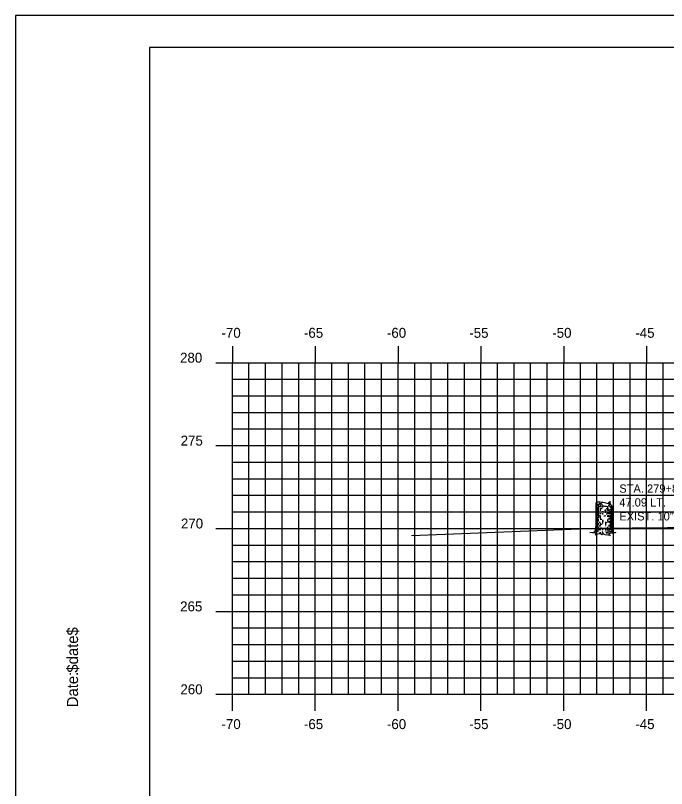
# Model space of a CAD drawing. Extents: x 854899 to 855069, y 366268 to 366378.
# Drawn here: x 854898.68 to 854937.97, y 366331.55 to 366378.18 of the extents above; entities that cross this region are included whole.
import ezdxf

# ---------------------------------------------------------------- set-up
doc = ezdxf.new("R2010")
doc.units = 0
for name, color, linetype in [('BORDER', 7, 'Continuous'), ('D_Text_Monospaced', 7, 'Continuous'), ('H_V ANNOTATION', 7, 'Continuous'), ('MAJOR', 7, 'Continuous'), ('MINOR', 7, 'Continuous'), ('PLOT BOUNDARY', 7, 'Continuous'), ('S_Roadway_Centerline', 7, 'Continuous'), ('S_Trees_Decid_NonPay', 7, 'Continuous')]:
    doc.layers.add(name, color=color, linetype=linetype)

msp = doc.modelspace()

# ---------------------------------------------------------------- linework, layer by layer
at = {"layer": 'BORDER'}
for p, q in [((855066.774, 366376.236), (854906.774, 366376.236)), ((854906.774, 366376.236), (854906.774, 366271.236))]:
    msp.add_line(p, q, dxfattribs=at)
at = {"layer": 'MAJOR'}
for p, q in [((854911.774, 366358.238), (854911.774, 366357.236)), ((854916.774, 366358.238), (854916.774, 366357.236)), ((854921.774, 366358.238), (854921.774, 366357.236)), ((854926.774, 366358.238), (854926.774, 366357.236)), ((854931.774, 366358.238), (854931.774, 366357.236)), ((854936.774, 366358.238), (854936.774, 366357.236)), ((854910.772, 366357.236), (854911.774, 366357.236)), ((854911.774, 366357.236), (855051.774, 366357.236)), ((854911.774, 366337.236), (854911.774, 366357.236)), ((854911.774, 366337.236), (854911.774, 366357.236)), ((854911.774, 366357.236), (855051.774, 366357.236)), ((854916.774, 366337.236), (854916.774, 366357.236)), ((854921.774, 366337.236), (854921.774, 366357.236)), ((854926.774, 366337.236), (854926.774, 366357.236)), ((854931.774, 366337.236), (854931.774, 366357.236)), ((854936.774, 366337.236), (854936.774, 366357.236)), ((854910.772, 366352.236), (854911.774, 366352.236)), ((854911.774, 366352.236), (855051.774, 366352.236)), ((854910.772, 366347.236), (854911.774, 366347.236)), ((854911.774, 366347.236), (855051.774, 366347.236)), ((854910.772, 366342.236), (854911.774, 366342.236)), ((854911.774, 366342.236), (855051.774, 366342.236)), ((854910.772, 366337.236), (854911.774, 366337.236)), ((854911.774, 366337.236), (855051.774, 366337.236)), ((854911.774, 366337.236), (855051.774, 366337.236)), ((854911.774, 366336.234), (854911.774, 366337.236)), ((854916.774, 366336.234), (854916.774, 366337.236)), ((854921.774, 366336.234), (854921.774, 366337.236)), ((854926.774, 366336.234), (854926.774, 366337.236)), ((854931.774, 366336.234), (854931.774, 366337.236)), ((854936.774, 366336.234), (854936.774, 366337.236))]:
    msp.add_line(p, q, dxfattribs=at)
at = {"layer": 'MINOR'}
for p, q in [((854911.774, 366337.236), (854911.774, 366357.236)), ((854912.774, 366337.236), (854912.774, 366357.236)), ((854913.774, 366337.236), (854913.774, 366357.236)), ((854914.774, 366337.236), (854914.774, 366357.236)), ((854915.774, 366337.236), (854915.774, 366357.236)), ((854917.774, 366337.236), (854917.774, 366357.236)), ((854918.774, 366337.236), (854918.774, 366357.236)), ((854919.774, 366337.236), (854919.774, 366357.236)), ((854920.774, 366337.236), (854920.774, 366357.236)), ((854922.774, 366337.236), (854922.774, 366357.236)), ((854923.774, 366337.236), (854923.774, 366357.236)), ((854924.774, 366337.236), (854924.774, 366357.236)), ((854925.774, 366337.236), (854925.774, 366357.236)), ((854927.774, 366337.236), (854927.774, 366357.236)), ((854928.774, 366337.236), (854928.774, 366357.236)), ((854929.774, 366337.236), (854929.774, 366357.236)), ((854930.774, 366337.236), (854930.774, 366357.236)), ((854932.774, 366337.236), (854932.774, 366357.236)), ((854933.774, 366337.236), (854933.774, 366357.236)), ((854934.774, 366337.236), (854934.774, 366357.236)), ((854935.774, 366337.236), (854935.774, 366357.236)), ((854937.774, 366337.236), (854937.774, 366357.236)), ((854911.774, 366356.236), (855051.774, 366356.236)), ((854911.774, 366356.236), (854912.776, 366356.236)), ((854911.774, 366355.236), (855051.774, 366355.236)), ((854911.774, 366355.236), (854912.776, 366355.236)), ((854911.774, 366354.236), (855051.774, 366354.236)), ((854911.774, 366354.236), (854912.776, 366354.236)), ((854911.774, 366353.236), (855051.774, 366353.236)), ((854911.774, 366353.236), (854912.776, 366353.236)), ((854911.774, 366351.236), (855051.774, 366351.236)), ((854911.774, 366351.236), (854912.776, 366351.236)), ((854911.774, 366350.236), (855051.774, 366350.236)), ((854911.774, 366350.236), (854912.776, 366350.236)), ((854911.774, 366349.236), (855051.774, 366349.236)), ((854911.774, 366349.236), (854912.776, 366349.236)), ((854911.774, 366348.236), (855051.774, 366348.236)), ((854911.774, 366348.236), (854912.776, 366348.236)), ((854911.774, 366346.236), (855051.774, 366346.236)), ((854911.774, 366346.236), (854912.776, 366346.236)), ((854911.774, 366345.236), (855051.774, 366345.236)), ((854911.774, 366345.236), (854912.776, 366345.236)), ((854911.774, 366344.236), (855051.774, 366344.236)), ((854911.774, 366344.236), (854912.776, 366344.236)), ((854911.774, 366343.236), (855051.774, 366343.236)), ((854911.774, 366343.236), (854912.776, 366343.236)), ((854911.774, 366341.236), (855051.774, 366341.236)), ((854911.774, 366341.236), (854912.776, 366341.236)), ((854911.774, 366340.236), (855051.774, 366340.236)), ((854911.774, 366340.236), (854912.776, 366340.236)), ((854911.774, 366339.236), (855051.774, 366339.236)), ((854911.774, 366339.236), (854912.776, 366339.236)), ((854911.774, 366338.236), (855051.774, 366338.236)), ((854911.774, 366338.236), (854912.776, 366338.236))]:
    msp.add_line(p, q, dxfattribs=at)
at = {"layer": 'PLOT BOUNDARY'}
msp.add_lwpolyline([(854898.681, 366268.177), (855068.681, 366268.177), (855068.681, 366378.177), (854898.681, 366378.177)], close=True, dxfattribs=at)
at = {"layer": 'S_Roadway_Centerline'}
msp.add_lwpolyline([(854922.581, 366346.808), (854933.213, 366347.24), (854933.77, 366347.25), (854944.438, 366347.363), (854959.926, 366347.522), (854961.662, 366347.525), (854964.949, 366347.208), (854965.329, 366347.182), (854971.014, 366347.57), (854971.53, 366347.601), (854971.79, 366347.613), (854982.395, 366348.069), (854983.385, 366348.065), (854993.304, 366347.931), (854996.962, 366347.86), (855000.308, 366347.852), (855002.655, 366347.97), (855005.503, 366347.986), (855011.351, 366348.088)], dxfattribs=at)
at = {"layer": 'S_Trees_Decid_NonPay'}
for p, q in [((854933.78, 366348.732), (854933.78, 366348.637)), ((854933.848, 366348.645), (854933.848, 366348.344)), ((854933.967, 366348.662), (854933.967, 366348.514)), ((854933.967, 366348.466), (854933.967, 366348.297)), ((854934.114, 366348.616), (854934.114, 366348.509)), ((854934.411, 366348.564), (854934.411, 366348.485)), ((854934.569, 366348.553), (854934.569, 366348.501)), ((854934.611, 366348.558), (854934.611, 366348.341)), ((854934.638, 366348.488), (854934.638, 366348.406)), ((854933.78, 366348.411), (854933.78, 366348.328)), ((854933.78, 366348.258), (854933.78, 366348.007)), ((854933.848, 366348.316), (854933.848, 366348.184)), ((854933.848, 366348.15), (854933.848, 366347.869)), ((854933.967, 366347.991), (854933.967, 366347.842)), ((854934.114, 366348.281), (854934.114, 366348.194)), ((854934.114, 366348.159), (854934.114, 366348.089)), ((854934.294, 366348.38), (854934.294, 366348.18)), ((854934.411, 366348.398), (854934.411, 366348.314)), ((854934.411, 366348.203), (854934.411, 366348.102)), ((854934.411, 366348.017), (854934.411, 366347.941)), ((854934.498, 366348.38), (854934.498, 366348.293)), ((854934.498, 366348.223), (854934.498, 366348.102)), ((854934.498, 366348.026), (854934.498, 366347.912)), ((854934.569, 366348.398), (854934.569, 366348.316)), ((854934.569, 366348.281), (854934.569, 366348.207)), ((854934.569, 366348.18), (854934.569, 366348.12)), ((854934.569, 366348.067), (854934.569, 366347.886)), ((854934.611, 366348.272), (854934.611, 366348.12)), ((854934.611, 366348.015), (854934.611, 366347.937)), ((854934.638, 366348.337), (854934.638, 366348.207)), ((854934.638, 366348.184), (854934.638, 366348.003)), ((854934.638, 366347.955), (854934.638, 366347.709)), ((854933.78, 366347.924), (854933.78, 366347.694)), ((854933.78, 366347.624), (854933.78, 366347.463)), ((854933.848, 366347.799), (854933.848, 366347.655)), ((854933.848, 366347.585), (854933.848, 366347.443)), ((854933.967, 366347.573), (854933.967, 366347.42)), ((854934.114, 366347.756), (854934.114, 366347.533)), ((854934.294, 366347.642), (854934.294, 366347.455)), ((854934.411, 366347.756), (854934.411, 366347.659)), ((854934.498, 366347.85), (854934.498, 366347.768)), ((854934.498, 366347.682), (854934.498, 366347.585)), ((854934.569, 366347.854), (854934.569, 366347.772)), ((854934.569, 366347.718), (854934.569, 366347.548)), ((854934.569, 366347.514), (854934.569, 366347.235)), ((854934.611, 366347.91), (854934.611, 366347.803)), ((854934.611, 366347.768), (854934.611, 366347.667)), ((854934.611, 366347.642), (854934.611, 366347.459)), ((854934.638, 366347.69), (854934.638, 366347.595)), ((854934.64, 366347.542), (854934.639, 366347.282)), ((854933.78, 366347.447), (854933.78, 366347.342)), ((854933.78, 366347.305), (854933.78, 366347.181)), ((854933.848, 366347.101), (854933.806, 366347.005)), ((854933.848, 366347.342), (854933.848, 366347.161)), ((854933.967, 366347.208), (854933.967, 366347.13)), ((854934.114, 366347.2), (854934.114, 366347.134)), ((854934.154, 366346.914), (854934.119, 366347.06)), ((854934.294, 366347.424), (854934.294, 366347.371)), ((854934.294, 366347.195), (854934.294, 366347.105)), ((854934.411, 366347.334), (854934.411, 366347.11)), ((854934.498, 366347.455), (854934.498, 366347.356)), ((854934.498, 366347.227), (854934.498, 366347.169)), ((854934.569, 366347.182), (854934.569, 366347.157)), ((854934.609, 366347.117), (854934.644, 366347.066)), ((854934.611, 366347.356), (854934.611, 366347.165)), ((854934.691, 366346.996), (854934.624, 366347.027)), ((854934.638, 366347.243), (854934.638, 366347.169))]:
    msp.add_line(p, q, dxfattribs=at)
for points in [[(854934.68, 366348.596), (854934.68, 366347.184), (854934.702, 366347.035), (854934.905, 366346.992), (854934.766, 366346.957), (854934.547, 366346.938), (854934.477, 366346.895), (854934.599, 366346.806), (854934.268, 366346.85), (854934.154, 366346.914), (854934.061, 366346.854), (854934.006, 366346.932), (854934.014, 366346.969), (854933.953, 366346.971), (854933.901, 366346.914), (854933.668, 366346.862), (854933.796, 366346.951), (854933.664, 366346.953), (854933.355, 366346.99), (854933.594, 366347.021), (854933.672, 366347.079), (854933.711, 366347.2), (854933.728, 366347.554), (854933.728, 366348.787)], [(854934.092, 366348.621), (854934.084, 366348.688), (854934.06, 366348.693), (854934.051, 366348.728), (854934.02, 366348.713), (854934.006, 366348.728), (854933.981, 366348.705), (854933.958, 366348.713), (854933.946, 366348.762), (854933.938, 366348.719), (854933.907, 366348.728), (854933.904, 366348.676)], [(854934.562, 366348.552), (854934.545, 366348.614), (854934.523, 366348.602), (854934.492, 366348.637), (854934.458, 366348.559)], [(854934.584, 366348.676), (854934.581, 366348.771), (854934.566, 366348.744), (854934.566, 366348.865), (854934.545, 366348.802), (854934.531, 366348.835), (854934.514, 366348.779), (854934.498, 366348.796), (854934.479, 366348.787), (854934.46, 366348.72)], [(854933.777, 366347.138), (854933.769, 366347.062), (854933.691, 366347.012)], [(854934.302, 366347.056), (854934.302, 366347.019), (854934.353, 366346.988), (854934.371, 366346.938)], [(854934.414, 366347.062), (854934.42, 366346.992), (854934.483, 366346.98)], [(854934.561, 366347.027), (854934.518, 366347.062), (854934.51, 366347.11)], [(854934.64, 366347.043), (854934.561, 366347.027), (854934.545, 366346.984)]]:
    msp.add_lwpolyline(points, dxfattribs=at)
for centre, radius, start, end in [((854933.746, 366348.787), 0.0179, 168.1723, 184.2278), ((854933.752, 366348.788), 0.0237, 184.2278, 198.1723), ((854933.747, 366348.64), 0.0191, 163.9485, 180), ((854933.747, 366348.64), 0.0191, 180, 196.0515), ((854933.753, 366348.642), 0.0252, 196.0515, 210), ((854933.747, 366348.426), 0.0191, 163.9485, 180), ((854933.747, 366348.426), 0.0191, 180, 196.0515), ((854933.753, 366348.428), 0.0252, 196.0515, 210), ((854933.746, 366348.787), 0.0179, 152.1168, 168.1723), ((854933.762, 366348.791), 0.0336, 198.1723, 216.9486), ((854933.751, 366348.785), 0.0237, 138.1723, 152.1168), ((854933.762, 366348.647), 0.0356, 210, 228.7494), ((854933.759, 366348.778), 0.0336, 119.396, 138.1723), ((854933.809, 366348.827), 0.0935, 216.9486, 228.1723), ((854933.803, 366348.694), 0.0984, 228.7494, 240), ((854933.788, 366348.726), 0.0935, 108.1723, 119.396), ((854933.962, 366348.997), 0.322, 228.1723, 250.2902), ((854933.917, 366348.891), 0.326, 240, 248.3243), ((854933.917, 366348.778), 0.326, 240.9099, 257.8036), ((854933.859, 366348.509), 0.322, 86.0543, 108.1723), ((854933.917, 366348.891), 0.326, 257.8036, 261.8968), ((854934.699, 366351.054), 2.507, 250.2902, 251.5281), ((854934.203, 366350.901), 2.356, 261.8968, 263.2799), ((854933.709, 366346.329), 2.507, 78.1723, 86.0543), ((854934.203, 366350.788), 2.356, 264.242, 267.3673), ((854934.203, 366350.901), 2.356, 265.24, 267.8386), ((854934.699, 366351.054), 2.507, 255.9987, 258.1723), ((854934.699, 366351.054), 2.507, 258.1723, 264.5013), ((854933.709, 366346.329), 2.507, 70.2902, 78.1723), ((854934.203, 366350.788), 2.356, 273.1481, 276.7734), ((854934.446, 366348.386), 0.322, 48.1723, 70.2902), ((854934.548, 366348.874), 0.322, 272.4479, 288.1723), ((854934.489, 366348.778), 0.326, 291.9506, 300), ((854934.619, 366348.657), 0.0935, 288.1723, 299.396), ((854934.603, 366348.581), 0.0984, 300, 311.2506), ((854934.598, 366348.556), 0.0935, 36.9486, 48.1723), ((854934.649, 366348.605), 0.0336, 299.396, 318.1723), ((854934.645, 366348.534), 0.0356, 311.2506, 330), ((854934.646, 366348.592), 0.0336, 18.1723, 36.9486), ((854934.656, 366348.599), 0.0237, 318.1723, 332.1168), ((854934.654, 366348.528), 0.0252, 330, 343.9485), ((854934.654, 366348.428), 0.0252, 330, 343.9485), ((854934.661, 366348.596), 0.0179, 332.1168, 348.1723), ((854934.656, 366348.595), 0.0237, 4.2278, 18.1723), ((854934.659, 366348.527), 0.0191, 360, 6.1128), ((854934.659, 366348.527), 0.0191, 343.9485, 360), ((854934.659, 366348.426), 0.0191, 360, 6.1128), ((854934.659, 366348.426), 0.0191, 343.9485, 360), ((854934.661, 366348.596), 0.0179, 348.1723, 4.2278), ((854933.747, 366348.323), 0.0191, 163.9485, 180), ((854933.747, 366348.323), 0.0191, 180, 196.0515), ((854933.753, 366348.325), 0.0252, 196.0515, 210), ((854933.747, 366348.103), 0.0191, 163.9485, 180), ((854933.747, 366348.103), 0.0191, 180, 196.0515), ((854933.753, 366348.105), 0.0252, 196.0515, 210), ((854933.747, 366347.988), 0.0191, 163.9485, 180), ((854933.747, 366347.988), 0.0191, 180, 196.0515), ((854933.753, 366347.99), 0.0252, 196.0515, 210), ((854933.762, 366348.433), 0.0356, 210, 228.7494), ((854933.762, 366348.33), 0.0356, 210, 228.7494), ((854933.762, 366348.11), 0.0356, 210, 228.7494), ((854933.762, 366347.995), 0.0356, 210, 228.7494), ((854933.803, 366348.48), 0.0984, 228.7494, 240), ((854933.803, 366348.377), 0.0984, 228.7494, 240), ((854933.803, 366348.157), 0.0984, 228.7494, 240), ((854933.804, 366348.043), 0.0984, 228.7494, 240), ((854933.917, 366348.677), 0.326, 240, 243.5719), ((854933.917, 366348.574), 0.326, 240, 243.243), ((854933.917, 366348.354), 0.326, 240, 245.1545), ((854933.918, 366348.24), 0.326, 240, 247.8656), ((854933.917, 366348.469), 0.326, 245.1545, 257.8036), ((854933.917, 366348.677), 0.326, 250.4167, 261.8968), ((854933.917, 366348.574), 0.326, 251.6831, 257.8036), ((854934.203, 366350.687), 2.356, 261.8968, 262.5519), ((854934.203, 366350.364), 2.356, 262.6588, 264.7911), ((854934.203, 366350.479), 2.356, 263.2682, 265.6362), ((854934.203, 366350.584), 2.356, 263.3413, 264.9946), ((854934.203, 366350.584), 2.356, 266.5036, 267.8386), ((854934.203, 366350.364), 2.356, 269.5578, 270), ((854934.203, 366350.364), 2.356, 270, 272.414), ((854934.203, 366350.687), 2.356, 270.8119, 272.1981), ((854934.203, 366350.584), 2.356, 272.1981, 273.9741), ((854934.203, 366350.479), 2.356, 273.0067, 275.0647), ((854934.203, 366350.687), 2.356, 275.0647, 278.1032), ((854934.203, 366350.364), 2.356, 275.0647, 277.1868), ((854934.203, 366350.479), 2.356, 277.1868, 278.1032), ((854934.203, 366350.584), 2.356, 277.3838, 278.1032), ((854934.489, 366348.677), 0.326, 278.1032, 279.0854), ((854934.489, 366348.574), 0.326, 278.1032, 284.0382), ((854934.489, 366348.469), 0.326, 278.1032, 284.0382), ((854934.489, 366348.354), 0.326, 284.0382, 300), ((854934.489, 366348.677), 0.326, 291.9506, 300), ((854934.489, 366348.469), 0.326, 291.9506, 300), ((854934.49, 366348.24), 0.326, 297.0058, 300), ((854934.603, 366348.48), 0.0984, 300, 311.2506), ((854934.603, 366348.272), 0.0984, 300, 311.2506), ((854934.603, 366348.157), 0.0984, 300, 311.2506), ((854934.604, 366348.043), 0.0984, 300, 311.2506), ((854934.645, 366348.433), 0.0356, 311.2506, 330), ((854934.645, 366348.225), 0.0356, 311.2506, 330), ((854934.645, 366348.11), 0.0356, 311.2506, 330), ((854934.645, 366347.995), 0.0356, 311.2506, 330), ((854934.654, 366348.22), 0.0252, 330, 343.9485), ((854934.654, 366348.105), 0.0252, 330, 343.9485), ((854934.654, 366347.99), 0.0252, 330, 343.9485), ((854934.659, 366348.323), 0.0191, 360, 6.1128), ((854934.659, 366348.323), 0.0191, 343.9485, 360), ((854934.659, 366348.218), 0.0191, 360, 6.1128), ((854934.659, 366348.218), 0.0191, 343.9485, 360), ((854934.659, 366348.103), 0.0191, 360, 6.1128), ((854934.659, 366348.103), 0.0191, 343.9485, 360), ((854934.66, 366347.988), 0.0191, 0, 6.1128), ((854934.66, 366347.988), 0.0191, 343.9485, 360), ((854933.744, 366347.888), 0.0191, 163.9485, 180), ((854933.747, 366347.783), 0.0191, 163.9485, 180), ((854933.747, 366347.783), 0.0191, 180, 196.0515), ((854933.753, 366347.785), 0.0252, 196.0515, 210), ((854933.762, 366347.79), 0.0356, 210, 228.7494), ((854933.803, 366347.838), 0.0984, 228.7494, 240), ((854933.915, 366348.14), 0.326, 240, 256.9079), ((854933.917, 366348.035), 0.326, 240, 245.1545), ((854933.917, 366347.944), 0.326, 241.939, 253.9183), ((854933.918, 366348.24), 0.326, 257.6699, 261.8968), ((854934.204, 366350.25), 2.356, 261.8968, 262.8615), ((854934.203, 366349.954), 2.356, 262.5843, 264.4865), ((854934.203, 366349.841), 2.356, 264.242, 267.469), ((854934.201, 366350.15), 2.356, 264.3443, 266.8529), ((854934.203, 366350.045), 2.356, 267.8386, 269.0054), ((854934.203, 366349.954), 2.356, 272.1981, 275.2726), ((854934.201, 366350.15), 2.356, 274.9734, 277.2455), ((854934.203, 366350.045), 2.356, 275.0647, 276.428), ((854934.49, 366348.24), 0.326, 283.9036, 291.8098), ((854934.489, 366348.035), 0.326, 284.0382, 291.9506), ((854934.489, 366347.831), 0.326, 284.0382, 291.9506), ((854934.487, 366348.14), 0.326, 292.4049, 300), ((854934.489, 366348.035), 0.326, 297.1525, 300), ((854934.601, 366347.942), 0.0984, 300, 311.2506), ((854934.603, 366347.838), 0.0984, 300, 311.2506), ((854934.642, 366347.895), 0.0356, 311.2506, 330), ((854934.645, 366347.79), 0.0356, 311.2506, 330), ((854934.651, 366347.89), 0.0252, 330, 343.9485), ((854934.657, 366347.888), 0.0191, 343.9485, 360), ((854934.654, 366347.785), 0.0252, 330, 343.9485), ((854934.657, 366347.888), 0.0191, 0, 6.1128), ((854934.659, 366347.783), 0.0191, 360, 6.1128), ((854934.659, 366347.783), 0.0191, 343.9485, 360), ((854934.659, 366347.693), 0.0191, 360, 6.1128), ((854933.732, 366347.244), 0.0191, 163.9485, 180), ((854933.732, 366347.244), 0.0191, 180, 196.0515), ((854933.738, 366347.245), 0.0252, 196.0515, 210), ((854933.747, 366347.25), 0.0356, 210, 228.7494), ((854933.738, 366347.354), 0.0191, 163.9485, 180), ((854933.738, 366347.354), 0.0191, 180, 196.0515), ((854933.744, 366347.356), 0.0252, 196.0515, 210), ((854933.753, 366347.361), 0.0356, 210, 228.7494), ((854933.743, 366347.464), 0.0191, 163.9485, 180), ((854933.743, 366347.464), 0.0191, 180, 196.0515), ((854933.749, 366347.466), 0.0252, 196.0515, 210), ((854933.789, 366347.298), 0.0984, 228.7494, 240), ((854933.758, 366347.471), 0.0356, 210, 228.7494), ((854933.794, 366347.408), 0.0984, 228.7494, 240), ((854933.799, 366347.519), 0.0984, 228.7494, 240), ((854933.903, 366347.495), 0.326, 240, 247.9161), ((854933.908, 366347.605), 0.326, 240, 241.9097), ((854933.913, 366347.716), 0.326, 240, 245.9375), ((854933.903, 366347.495), 0.326, 260.3834, 261.8968), ((854934.189, 366349.505), 2.356, 261.8968, 263.5333), ((854934.199, 366349.726), 2.356, 262.2226, 264.4852), ((854934.194, 366349.615), 2.356, 264.9089, 266.8158), ((854934.194, 366349.615), 2.356, 274.1864, 275.2829), ((854934.189, 366349.505), 2.356, 274.5551, 275.4167), ((854934.199, 366349.726), 2.356, 277.2863, 278.1032), ((854934.189, 366349.505), 2.356, 277.5403, 278.1032), ((854934.475, 366347.495), 0.326, 278.1032, 294.7094), ((854934.485, 366347.716), 0.326, 278.1032, 284.7741), ((854934.48, 366347.605), 0.326, 293.6544, 300), ((854934.589, 366347.298), 0.0984, 300, 311.2506), ((854934.599, 366347.519), 0.0984, 300, 311.2506), ((854934.63, 366347.25), 0.0356, 311.2506, 330), ((854934.639, 366347.245), 0.0252, 330, 343.9485), ((854934.645, 366347.244), 0.0191, 343.9485, 360), ((854934.64, 366347.471), 0.0356, 311.2506, 330), ((854934.645, 366347.244), 0.0191, 0, 6.1128), ((854934.65, 366347.466), 0.0252, 330, 343.9485), ((854934.655, 366347.464), 0.0191, 360, 6.1128), ((854934.655, 366347.464), 0.0191, 343.9485, 360)]:
    msp.add_arc(centre, radius, start, end, dxfattribs=at)

# ---------------------------------------------------------------- texts
at = {"layer": 'BORDER'}
for s, p in [('$date$', (854902.459, 366338.542)), ('Date:', (854902.459, 366336.453))]:
    msp.add_text(s, height=0.6696, rotation=90, dxfattribs=at).set_placement(p)
at = {"layer": 'D_Text_Monospaced'}
for s, height, p in [('STA. 279+80.66', 0.49998, (854935.123, 366349.394)), ('47.09 LT.', 0.5, (854935.123, 366348.56)), ('EXIST. 10" TRIPLE BIRCH', 0.49998, (854935.123, 366347.72))]:
    msp.add_text(s, height=height, dxfattribs=at).set_placement(p)
at = {"layer": 'H_V ANNOTATION'}
for s, p in [('-70', (854911.116, 366358.736)), ('-65', (854916.092, 366358.736)), ('-60', (854921.1, 366358.736)), ('-55', (854926.07, 366358.736)), ('-50', (854931.078, 366358.736)), ('-45', (854936.092, 366358.736)), ('280', (854908.615, 366357.236)), ('275', (854908.652, 366352.236)), ('270', (854908.668, 366347.236)), ('265', (854908.62, 366342.236)), ('260', (854908.636, 366337.236)), ('-70', (854911.116, 366335.136)), ('-65', (854916.092, 366335.136)), ('-60', (854921.1, 366335.136)), ('-55', (854926.07, 366335.136)), ('-50', (854931.078, 366335.136)), ('-45', (854936.092, 366335.136))]:
    msp.add_text(s, height=0.6, dxfattribs=at).set_placement(p)

doc.saveas('drawing.dxf')
